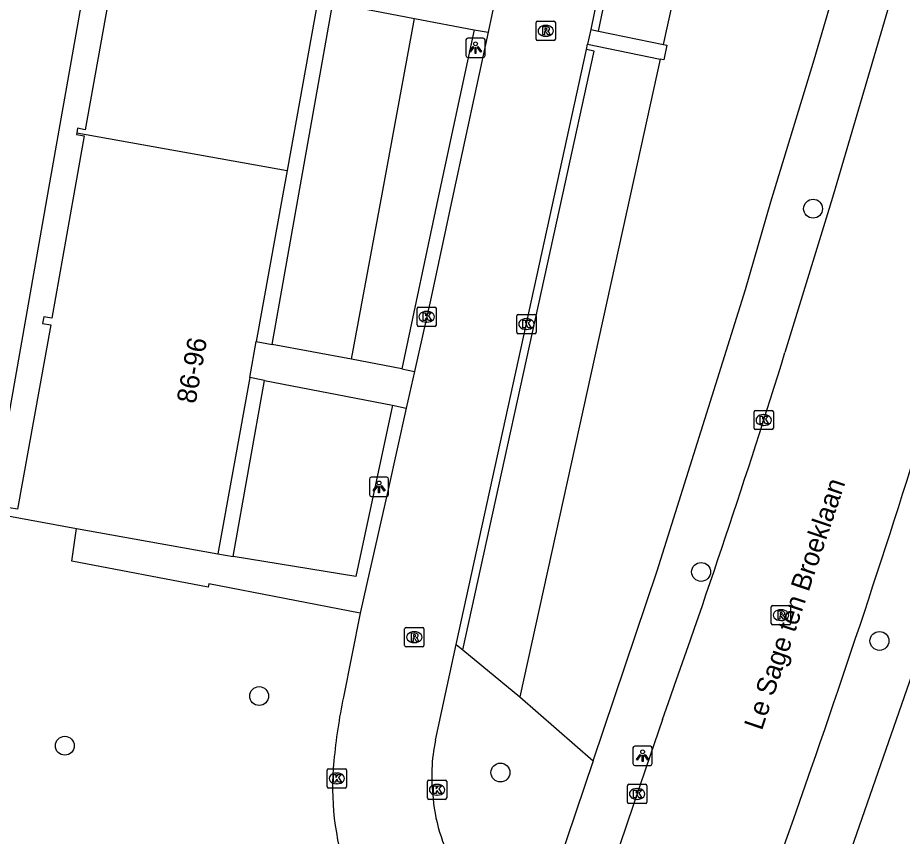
# Model space of a CAD drawing. Extents: x 161402 to 161933, y 381650 to 382313.
# Drawn here: x 161719.23 to 161765.07, y 381716.7 to 381759.14 of the extents above; entities that cross this region are included whole.
import ezdxf

# ---------------------------------------------------------------- set-up
doc = ezdxf.new("R2010")
doc.units = 0
for name, color, linetype in [('IMGEO_Boom', 7, 'Continuous'), ('IMGEO_Groenvoorziening', 7, 'Continuous'), ('IMGEO_Haag', 7, 'Continuous'), ('IMGEO_Kolk', 7, 'Continuous'), ('IMGEO_Lichtpunt', 7, 'Continuous'), ('IMGEO_Openbare_ruimte_label', 7, 'Continuous'), ('IMGEO_Pand', 7, 'Continuous'), ('IMGEO_Pand_nummerreeks', 7, 'Continuous'), ('IMGEO_Rijbaan_lokaal_open', 7, 'Continuous'), ('IMGEO_Rioolput', 7, 'Continuous'), ('IMGEO_Voetpad_halfverhard', 7, 'Continuous'), ('IMGEO_Voetpad_open', 7, 'Continuous')]:
    doc.layers.add(name, color=color, linetype=linetype)

msp = doc.modelspace()

# ---------------------------------------------------------------- linework, layer by layer
at = {"layer": 'IMGEO_Boom'}
for centre in [(161760.441, 381749.242), (161754.64, 381730.411), (161763.88, 381726.834), (161731.741, 381723.975), (161721.671, 381721.4), (161744.243, 381720.011)]:
    msp.add_circle(centre, 0.489, dxfattribs=at)
at = {"layer": 'IMGEO_Groenvoorziening'}
for points in [[(161725.367, 381800.387), (161728.333, 381792.761), (161720.782, 381750), (161715.379, 381719.409), (161702.956, 381716.799)], [(161752.695, 381757.755), (161756.802, 381776.413)], [(161736.533, 381741.432), (161738.116, 381750), (161739.797, 381759.102)], [(161752.527, 381756.994), (161750.987, 381750), (161745.247, 381723.935)], [(161742.303, 381726.365), (161745.247, 381723.935)], [(161745.247, 381723.935), (161749.043, 381720.61)]]:
    msp.add_lwpolyline(points, dxfattribs=at)
at = {"layer": 'IMGEO_Haag'}
for points in [[(161749.327, 381758.447), (161752.919, 381775.683)], [(161742.303, 381726.365), (161747.467, 381749.915), (161749.101, 381757.409), (161748.698, 381757.489)], [(161741.956, 381726.652), (161742.303, 381726.365)]]:
    msp.add_lwpolyline(points, dxfattribs=at)
at = {"layer": 'IMGEO_Kolk'}
for p, q in [((161739.921, 381743.212), (161739.921, 381744.064)), ((161739.996, 381744.138), (161740.848, 381744.138)), ((161740.409, 381743.918), (161740.434, 381743.918)), ((161740.922, 381744.064), (161740.922, 381743.212)), ((161740.432, 381743.358), (161740.407, 381743.358)), ((161745.09, 381742.836), (161745.09, 381743.688)), ((161745.165, 381743.762), (161746.017, 381743.762)), ((161745.578, 381743.542), (161745.603, 381743.542)), ((161746.091, 381743.688), (161746.091, 381742.836)), ((161740.848, 381743.138), (161739.996, 381743.138)), ((161745.601, 381742.982), (161745.576, 381742.982)), ((161746.017, 381742.762), (161745.165, 381742.762)), ((161757.46, 381738.786), (161758.312, 381738.786)), ((161757.385, 381737.86), (161757.385, 381738.712)), ((161757.873, 381738.566), (161757.898, 381738.566)), ((161758.386, 381738.712), (161758.386, 381737.86)), ((161757.896, 381738.006), (161757.871, 381738.006)), ((161758.312, 381737.786), (161757.46, 381737.786)), ((161735.266, 381719.28), (161735.266, 381720.132)), ((161735.341, 381720.206), (161736.193, 381720.206)), ((161735.754, 381719.986), (161735.779, 381719.986)), ((161736.267, 381720.132), (161736.267, 381719.28)), ((161740.461, 381718.693), (161740.461, 381719.545)), ((161740.536, 381719.619), (161741.388, 381719.619)), ((161741.462, 381719.545), (161741.462, 381718.693)), ((161736.193, 381719.206), (161735.341, 381719.206)), ((161735.777, 381719.426), (161735.752, 381719.426)), ((161740.949, 381719.399), (161740.974, 381719.399)), ((161750.825, 381718.474), (161750.825, 381719.326)), ((161750.9, 381719.4), (161751.752, 381719.4)), ((161751.313, 381719.18), (161751.338, 381719.18)), ((161751.826, 381719.326), (161751.826, 381718.474)), ((161741.388, 381718.619), (161740.536, 381718.619)), ((161740.972, 381718.839), (161740.947, 381718.839)), ((161751.336, 381718.62), (161751.311, 381718.62)), ((161751.752, 381718.4), (161750.9, 381718.4))]:
    msp.add_line(p, q, dxfattribs=at)
for points in [[(161739.921, 381743.212), (161739.921, 381744.064)], [(161739.996, 381744.138), (161740.848, 381744.138)], [(161740.242, 381743.838), (161740.365, 381743.838), (161740.365, 381743.687), (161740.495, 381743.838), (161740.659, 381743.838), (161740.513, 381743.687), (161740.666, 381743.438), (161740.514, 381743.438), (161740.429, 381743.602), (161740.365, 381743.535), (161740.365, 381743.438), (161740.242, 381743.438), (161740.242, 381743.838)], [(161740.922, 381744.064), (161740.922, 381743.212)], [(161745.09, 381742.836), (161745.09, 381743.688)], [(161745.165, 381743.762), (161746.017, 381743.762)], [(161745.411, 381743.462), (161745.534, 381743.462), (161745.534, 381743.311), (161745.664, 381743.462), (161745.828, 381743.462), (161745.682, 381743.311), (161745.835, 381743.062), (161745.683, 381743.062), (161745.598, 381743.226), (161745.534, 381743.159), (161745.534, 381743.062), (161745.411, 381743.062), (161745.411, 381743.462)], [(161746.091, 381743.688), (161746.091, 381742.836)], [(161740.848, 381743.138), (161739.996, 381743.138)], [(161746.017, 381742.762), (161745.165, 381742.762)], [(161757.46, 381738.786), (161758.312, 381738.786)], [(161757.385, 381737.86), (161757.385, 381738.712)], [(161757.706, 381738.486), (161757.829, 381738.486), (161757.829, 381738.335), (161757.959, 381738.486), (161758.123, 381738.486), (161757.977, 381738.335), (161758.13, 381738.086), (161757.978, 381738.086), (161757.893, 381738.25), (161757.829, 381738.183), (161757.829, 381738.086), (161757.706, 381738.086), (161757.706, 381738.486)], [(161758.386, 381738.712), (161758.386, 381737.86)], [(161758.312, 381737.786), (161757.46, 381737.786)], [(161735.266, 381719.28), (161735.266, 381720.132)], [(161735.341, 381720.206), (161736.193, 381720.206)], [(161736.267, 381720.132), (161736.267, 381719.28)], [(161735.587, 381719.906), (161735.71, 381719.906), (161735.71, 381719.755), (161735.84, 381719.906), (161736.004, 381719.906), (161735.858, 381719.755), (161736.011, 381719.506), (161735.859, 381719.506), (161735.774, 381719.67), (161735.71, 381719.603), (161735.71, 381719.506), (161735.587, 381719.506), (161735.587, 381719.906)], [(161740.461, 381718.693), (161740.461, 381719.545)], [(161740.536, 381719.619), (161741.388, 381719.619)], [(161741.462, 381719.545), (161741.462, 381718.693)], [(161736.193, 381719.206), (161735.341, 381719.206)], [(161740.782, 381719.319), (161740.905, 381719.319), (161740.905, 381719.168), (161741.035, 381719.319), (161741.199, 381719.319), (161741.053, 381719.168), (161741.206, 381718.919), (161741.054, 381718.919), (161740.969, 381719.083), (161740.905, 381719.016), (161740.905, 381718.919), (161740.782, 381718.919), (161740.782, 381719.319)], [(161750.825, 381718.474), (161750.825, 381719.326)], [(161750.9, 381719.4), (161751.752, 381719.4)], [(161751.146, 381719.1), (161751.269, 381719.1), (161751.269, 381718.949), (161751.399, 381719.1), (161751.563, 381719.1), (161751.417, 381718.949), (161751.57, 381718.7), (161751.418, 381718.7), (161751.333, 381718.864), (161751.269, 381718.797), (161751.269, 381718.7), (161751.146, 381718.7), (161751.146, 381719.1)], [(161751.826, 381719.326), (161751.826, 381718.474)], [(161741.388, 381718.619), (161740.536, 381718.619)], [(161751.752, 381718.4), (161750.9, 381718.4)]]:
    msp.add_lwpolyline(points, dxfattribs=at)
for centre, start, end in [((161739.998, 381744.062), 91.552, 178.448), ((161739.998, 381744.062), 91.552, 178.448), ((161740.846, 381744.062), 1.552, 88.448), ((161740.846, 381744.062), 1.552, 88.448), ((161745.167, 381743.686), 91.552, 178.448), ((161745.167, 381743.686), 91.552, 178.448), ((161746.015, 381743.686), 1.552, 88.448), ((161746.015, 381743.686), 1.552, 88.448), ((161739.998, 381743.214), 181.552, 268.448), ((161739.998, 381743.214), 181.552, 268.448), ((161740.846, 381743.214), 271.552, 358.448), ((161740.846, 381743.214), 271.552, 358.448), ((161745.167, 381742.838), 181.552, 268.448), ((161745.167, 381742.838), 181.552, 268.448), ((161746.015, 381742.838), 271.552, 358.448), ((161746.015, 381742.838), 271.552, 358.448), ((161757.462, 381738.71), 91.552, 178.448), ((161757.462, 381738.71), 91.552, 178.448), ((161758.31, 381738.71), 1.552, 88.448), ((161758.31, 381738.71), 1.552, 88.448), ((161757.462, 381737.862), 181.552, 268.448), ((161757.462, 381737.862), 181.552, 268.448), ((161758.31, 381737.862), 271.552, 358.448), ((161758.31, 381737.862), 271.552, 358.448), ((161735.343, 381720.13), 91.552, 178.448), ((161735.343, 381720.13), 91.552, 178.448), ((161736.191, 381720.13), 1.552, 88.448), ((161736.191, 381720.13), 1.552, 88.448), ((161740.538, 381719.543), 91.552, 178.448), ((161740.538, 381719.543), 91.552, 178.448), ((161741.386, 381719.543), 1.552, 88.448), ((161741.386, 381719.543), 1.552, 88.448), ((161735.343, 381719.282), 181.552, 268.448), ((161735.343, 381719.282), 181.552, 268.448), ((161736.191, 381719.282), 271.552, 358.448), ((161736.191, 381719.282), 271.552, 358.448), ((161750.902, 381719.324), 91.552, 178.448), ((161750.902, 381719.324), 91.552, 178.448), ((161751.75, 381719.324), 1.552, 88.448), ((161751.75, 381719.324), 1.552, 88.448), ((161740.538, 381718.695), 181.552, 268.448), ((161740.538, 381718.695), 181.552, 268.448), ((161741.386, 381718.695), 271.552, 358.448), ((161741.386, 381718.695), 271.552, 358.448), ((161750.902, 381718.476), 181.552, 268.448), ((161750.902, 381718.476), 181.552, 268.448), ((161751.75, 381718.476), 271.552, 358.448), ((161751.75, 381718.476), 271.552, 358.448)]:
    msp.add_arc(centre, 0.0765, start, end, dxfattribs=at)
for centre, major_axis, ratio, start_param, end_param in [((161740.408, 381743.638), (-0.387, 0.002), 0.722429, 4.712389, 7.853982), ((161740.433, 381743.638), (-0.39, 0.002), 0.717154, 1.570796, 4.712389), ((161745.577, 381743.262), (-0.387, 0.002), 0.722429, 4.712389, 7.853982), ((161745.602, 381743.262), (-0.39, 0.002), 0.717154, 1.570796, 4.712389), ((161757.872, 381738.286), (-0.387, 0.002), 0.722429, 4.712389, 7.853982), ((161757.897, 381738.286), (-0.39, 0.002), 0.717154, 1.570796, 4.712389), ((161735.753, 381719.706), (-0.387, 0.002), 0.722429, 4.712389, 7.853982), ((161735.778, 381719.706), (-0.39, 0.002), 0.717154, 1.570796, 4.712389), ((161740.948, 381719.119), (-0.387, 0.002), 0.722429, 4.712389, 7.853982), ((161740.973, 381719.119), (-0.39, 0.002), 0.717154, 1.570796, 4.712389), ((161751.312, 381718.9), (-0.387, 0.002), 0.722429, 4.712389, 7.853982), ((161751.337, 381718.9), (-0.39, 0.002), 0.717154, 1.570796, 4.712389)]:
    msp.add_ellipse(centre, major_axis=major_axis, ratio=ratio, start_param=start_param, end_param=end_param, dxfattribs=at)
at = {"layer": 'IMGEO_Lichtpunt'}
for p, q in [((161743.356, 381758.082), (161742.548, 381758.082)), ((161743.356, 381758.082), (161742.548, 381758.082)), ((161742.454, 381757.987), (161742.454, 381757.18)), ((161742.454, 381757.987), (161742.454, 381757.18)), ((161743.45, 381757.18), (161743.45, 381757.987)), ((161743.45, 381757.18), (161743.45, 381757.987)), ((161742.548, 381757.086), (161743.356, 381757.086)), ((161742.548, 381757.086), (161743.356, 381757.086)), ((161737.455, 381735.223), (161737.455, 381734.416)), ((161737.455, 381735.223), (161737.455, 381734.416)), ((161738.357, 381735.318), (161737.549, 381735.318)), ((161738.357, 381735.318), (161737.549, 381735.318)), ((161738.451, 381734.416), (161738.451, 381735.223)), ((161738.451, 381734.416), (161738.451, 381735.223)), ((161737.549, 381734.322), (161738.357, 381734.322)), ((161737.549, 381734.322), (161738.357, 381734.322)), ((161752.012, 381721.379), (161751.204, 381721.379)), ((161752.012, 381721.379), (161751.204, 381721.379)), ((161751.11, 381721.284), (161751.11, 381720.477)), ((161751.11, 381721.284), (161751.11, 381720.477)), ((161752.106, 381720.477), (161752.106, 381721.284)), ((161752.106, 381720.477), (161752.106, 381721.284)), ((161751.204, 381720.383), (161752.012, 381720.383)), ((161751.204, 381720.383), (161752.012, 381720.383))]:
    msp.add_line(p, q, dxfattribs=at)
for points in [[(161742.828, 381757.651), (161742.867, 381757.623), (161742.679, 381757.361), (161742.641, 381757.388), (161742.828, 381757.651)], [(161742.93, 381757.603), (161742.977, 381757.603), (161742.977, 381757.281), (161742.93, 381757.281), (161742.93, 381757.603)], [(161743.04, 381757.623), (161743.078, 381757.65), (161743.265, 381757.388), (161743.226, 381757.36), (161743.04, 381757.623)], [(161737.829, 381734.887), (161737.868, 381734.859), (161737.68, 381734.597), (161737.642, 381734.624), (161737.829, 381734.887)], [(161737.931, 381734.839), (161737.978, 381734.839), (161737.978, 381734.517), (161737.931, 381734.517), (161737.931, 381734.839)], [(161738.041, 381734.859), (161738.079, 381734.886), (161738.266, 381734.624), (161738.227, 381734.596), (161738.041, 381734.859)], [(161751.484, 381720.948), (161751.523, 381720.92), (161751.335, 381720.658), (161751.297, 381720.685), (161751.484, 381720.948)], [(161751.586, 381720.9), (161751.633, 381720.9), (161751.633, 381720.578), (161751.586, 381720.578), (161751.586, 381720.9)], [(161751.696, 381720.92), (161751.734, 381720.947), (161751.921, 381720.685), (161751.882, 381720.657), (161751.696, 381720.92)]]:
    msp.add_lwpolyline(points, dxfattribs=at)
for centre in [(161742.953, 381757.785), (161737.954, 381735.021), (161751.609, 381721.082)]:
    msp.add_circle(centre, 0.0994, dxfattribs=at)
for centre, start, end in [((161742.548, 381757.987), 90, 180), ((161742.548, 381757.987), 90, 180), ((161743.356, 381757.987), 0, 90), ((161743.356, 381757.987), 0, 90), ((161742.548, 381757.18), 180, 270), ((161742.548, 381757.18), 180, 270), ((161743.356, 381757.18), 270, 0), ((161743.356, 381757.18), 270, 360), ((161737.549, 381735.223), 90, 180), ((161737.549, 381735.223), 90, 180), ((161738.357, 381735.223), 0, 90), ((161738.357, 381735.223), 0, 90), ((161737.549, 381734.416), 180, 270), ((161737.549, 381734.416), 180, 270), ((161738.357, 381734.416), 270, 0), ((161738.357, 381734.416), 270, 360), ((161751.204, 381721.284), 90, 180), ((161751.204, 381721.284), 90, 180), ((161752.012, 381721.284), 0, 90), ((161752.012, 381721.284), 0, 90), ((161751.204, 381720.477), 180, 270), ((161751.204, 381720.477), 180, 270), ((161752.012, 381720.477), 270, 0), ((161752.012, 381720.477), 270, 360)]:
    msp.add_arc(centre, 0.0946, start, end, dxfattribs=at)
at = {"layer": 'IMGEO_Pand'}
for points in [[(161725.892, 381773.039), (161725.859, 381772.854), (161726.26, 381772.781), (161724.523, 381763.142), (161724.114, 381763.215), (161724.064, 381762.939), (161724.443, 381762.871), (161722.724, 381753.337), (161722.338, 381753.407), (161722.297, 381753.177)], [(161734.783, 381760.053), (161733.19, 381751.213)], [(161722.297, 381753.177), (161722.28, 381753.082), (161722.68, 381753.011), (161722.143, 381750), (161720.996, 381743.567), (161720.586, 381743.641), (161720.524, 381743.295), (161720.94, 381743.22), (161719.217, 381733.661), (161718.794, 381733.737), (161718.717, 381733.311), (161722.279, 381732.669)], [(161722.297, 381753.177), (161733.19, 381751.213)], [(161733.19, 381751.213), (161732.971, 381750), (161731.594, 381742.363)], [(161731.255, 381740.488), (161731.594, 381742.363)], [(161731.255, 381740.488), (161729.607, 381731.348)], [(161722.279, 381732.669), (161729.607, 381731.348)]]:
    msp.add_lwpolyline(points, dxfattribs=at)
at = {"layer": 'IMGEO_Rijbaan_lokaal_open'}
for points in [[(161754.814, 381786.734), (161752.712, 381777.049), (161748.925, 381758.53)], [(161770.158, 381780.913), (161765.505, 381763.644), (161761.5, 381750), (161761.259, 381749.201), (161758.985, 381741.778)], [(161743.993, 381760.2), (161743.602, 381758.386)], [(161748.925, 381758.53), (161748.758, 381757.763)], [(161743.602, 381758.386), (161741.798, 381750), (161740.649, 381744.661), (161739.789, 381740.808)], [(161748.698, 381757.489), (161748.758, 381757.763)], [(161741.956, 381726.652), (161747.061, 381750), (161748.698, 381757.489)], [(161739.789, 381740.808), (161739.363, 381738.9)], [(161739.363, 381738.9), (161738.423, 381734.691), (161737.326, 381729.802), (161736.974, 381728.265)], [(161736.974, 381728.265), (161736.105, 381723.922)], [(161740.88, 381721.689), (161741.956, 381726.652)], [(161752.637, 381722.762), (161751.781, 381720.237), (161748.444, 381710.397)], [(161750.867, 381693.658), (161751.631, 381695.709), (161754.863, 381704.566), (161757.922, 381713.379), (161759.437, 381717.619), (161760.349, 381720.224)]]:
    msp.add_lwpolyline(points, dxfattribs=at)
for centre, radius, start, end in [((161312.649, 381880.208), 467.31, 340.31066, 342.76883), ((161210.71, 381911.237), 581.883, 340.83641, 343.084251), ((161766.318, 381717.777), 30.832, 168.5045, 174.7269), ((161749.719, 381719.81), 9.037, 167.9975, 187.3155), ((161749.342, 381719.214), 13.796, 174.1902, 198.9774), ((161749.343, 381719.411), 8.62, 185.002, 211.8498)]:
    msp.add_arc(centre, radius, start, end, dxfattribs=at)
at = {"layer": 'IMGEO_Rioolput'}
for p, q in [((161746.165, 381758.963), (161747.017, 381758.963)), ((161746.09, 381758.037), (161746.09, 381758.889)), ((161746.578, 381758.743), (161746.603, 381758.743)), ((161747.091, 381758.889), (161747.091, 381758.037)), ((161746.601, 381758.183), (161746.576, 381758.183)), ((161747.017, 381757.963), (161746.165, 381757.963)), ((161758.278, 381727.745), (161758.278, 381728.597)), ((161758.353, 381728.671), (161759.205, 381728.671)), ((161758.766, 381728.451), (161758.791, 381728.451)), ((161759.279, 381728.597), (161759.279, 381727.745)), ((161758.789, 381727.891), (161758.764, 381727.891)), ((161739.281, 381726.601), (161739.281, 381727.453)), ((161739.356, 381727.527), (161740.208, 381727.527)), ((161740.282, 381727.453), (161740.282, 381726.601)), ((161759.205, 381727.671), (161758.353, 381727.671)), ((161739.769, 381727.307), (161739.794, 381727.307)), ((161740.208, 381726.527), (161739.356, 381726.527)), ((161739.792, 381726.747), (161739.767, 381726.747))]:
    msp.add_line(p, q, dxfattribs=at)
for points in [[(161746.165, 381758.963), (161747.017, 381758.963)], [(161746.09, 381758.037), (161746.09, 381758.889)], [(161746.679, 381758.661), (161746.427, 381758.663), (161746.427, 381758.263)], [(161746.605, 381758.582), (161746.551, 381758.582), (161746.551, 381758.501)], [(161746.551, 381758.501), (161746.603, 381758.501)], [(161747.091, 381758.889), (161747.091, 381758.037)], [(161746.427, 381758.263), (161746.551, 381758.263), (161746.551, 381758.425), (161746.562, 381758.425)], [(161746.609, 381758.396), (161746.68, 381758.263), (161746.82, 381758.263), (161746.755, 381758.389)], [(161747.017, 381757.963), (161746.165, 381757.963)], [(161758.278, 381727.745), (161758.278, 381728.597)], [(161758.353, 381728.671), (161759.205, 381728.671)], [(161758.867, 381728.369), (161758.615, 381728.371), (161758.615, 381727.971)], [(161758.793, 381728.29), (161758.739, 381728.29), (161758.739, 381728.209)], [(161759.279, 381728.597), (161759.279, 381727.745)], [(161758.615, 381727.971), (161758.739, 381727.971), (161758.739, 381728.133), (161758.75, 381728.133)], [(161758.739, 381728.209), (161758.791, 381728.209)], [(161758.797, 381728.104), (161758.868, 381727.971), (161759.008, 381727.971), (161758.943, 381728.097)], [(161739.281, 381726.601), (161739.281, 381727.453)], [(161739.356, 381727.527), (161740.208, 381727.527)], [(161740.282, 381727.453), (161740.282, 381726.601)], [(161759.205, 381727.671), (161758.353, 381727.671)], [(161739.87, 381727.225), (161739.618, 381727.227), (161739.618, 381726.827)], [(161739.618, 381726.827), (161739.742, 381726.827), (161739.742, 381726.989), (161739.753, 381726.989)], [(161739.796, 381727.146), (161739.742, 381727.146), (161739.742, 381727.065)], [(161739.742, 381727.065), (161739.794, 381727.065)], [(161739.8, 381726.96), (161739.871, 381726.827), (161740.011, 381726.827), (161739.946, 381726.953)], [(161740.208, 381726.527), (161739.356, 381726.527)]]:
    msp.add_lwpolyline(points, dxfattribs=at)
for centre, radius, start, end in [((161746.167, 381758.887), 0.0765, 91.552, 178.448), ((161746.167, 381758.887), 0.0765, 91.552, 178.448), ((161747.015, 381758.887), 0.0765, 1.552, 88.448), ((161747.015, 381758.887), 0.0765, 1.552, 88.448), ((161746.587, 381758.69), 0.19, 274.7715, 282.9687), ((161746.611, 381758.486), 0.0964, 77.0061, 93.1865), ((161746.625, 381758.543), 0.0378, 276.6634, 79.6772), ((161746.678, 381758.551), 0.109, 350.3612, 89.416), ((161746.676, 381758.551), 0.112, 277.5842, 350.9817), ((161746.167, 381758.039), 0.0765, 181.552, 268.448), ((161746.167, 381758.039), 0.0765, 181.552, 268.448), ((161746.561, 381758.372), 0.0533, 26.0293, 88.6989), ((161746.66, 381758.336), 0.108, 29.5134, 73.7905), ((161747.015, 381758.039), 0.0765, 271.552, 358.448), ((161747.015, 381758.039), 0.0765, 271.552, 358.448), ((161758.355, 381728.595), 0.0765, 91.552, 178.448), ((161758.355, 381728.595), 0.0765, 91.552, 178.448), ((161758.799, 381728.194), 0.0964, 77.0061, 93.1865), ((161758.813, 381728.251), 0.0378, 276.6634, 79.6772), ((161758.866, 381728.259), 0.109, 350.3612, 89.416), ((161758.864, 381728.259), 0.112, 277.5842, 350.9817), ((161759.203, 381728.595), 0.0765, 1.552, 88.448), ((161759.203, 381728.595), 0.0765, 1.552, 88.448), ((161758.749, 381728.08), 0.0533, 26.0293, 88.6989), ((161758.775, 381728.398), 0.19, 274.7715, 282.9687), ((161758.848, 381728.044), 0.108, 29.5134, 73.7905), ((161739.358, 381727.451), 0.0765, 91.552, 178.448), ((161739.358, 381727.451), 0.0765, 91.552, 178.448), ((161740.206, 381727.451), 0.0765, 1.552, 88.448), ((161740.206, 381727.451), 0.0765, 1.552, 88.448), ((161758.355, 381727.747), 0.0765, 181.552, 268.448), ((161758.355, 381727.747), 0.0765, 181.552, 268.448), ((161759.203, 381727.747), 0.0765, 271.552, 358.448), ((161759.203, 381727.747), 0.0765, 271.552, 358.448), ((161739.752, 381726.936), 0.0533, 26.0293, 88.6989), ((161739.778, 381727.254), 0.19, 274.7715, 282.9687), ((161739.802, 381727.05), 0.0964, 77.0061, 93.1865), ((161739.816, 381727.107), 0.0378, 276.6634, 79.6772), ((161739.869, 381727.115), 0.109, 350.3612, 89.416), ((161739.867, 381727.115), 0.112, 277.5842, 350.9817), ((161739.851, 381726.9), 0.108, 29.5134, 73.7905), ((161739.358, 381726.603), 0.0765, 181.552, 268.448), ((161739.358, 381726.603), 0.0765, 181.552, 268.448), ((161740.206, 381726.603), 0.0765, 271.552, 358.448), ((161740.206, 381726.603), 0.0765, 271.552, 358.448)]:
    msp.add_arc(centre, radius, start, end, dxfattribs=at)
for centre, major_axis, ratio, start_param, end_param in [((161746.577, 381758.463), (-0.387, 0.002), 0.722429, 4.712389, 7.853982), ((161746.602, 381758.463), (-0.39, 0.002), 0.717154, 1.570796, 4.712389), ((161758.765, 381728.171), (-0.387, 0.002), 0.722429, 4.712389, 7.853982), ((161758.79, 381728.171), (-0.39, 0.002), 0.717154, 1.570796, 4.712389), ((161739.768, 381727.027), (-0.387, 0.002), 0.722429, 4.712389, 7.853982), ((161739.793, 381727.027), (-0.39, 0.002), 0.717154, 1.570796, 4.712389)]:
    msp.add_ellipse(centre, major_axis=major_axis, ratio=ratio, start_param=start_param, end_param=end_param, dxfattribs=at)
at = {"layer": 'IMGEO_Voetpad_halfverhard'}
for points in [[(161732.415, 381742.208), (161733.8, 381750), (161735.559, 381759.906)], [(161730.391, 381731.218), (161732.017, 381740.34)]]:
    msp.add_lwpolyline(points, dxfattribs=at)
at = {"layer": 'IMGEO_Voetpad_open'}
for points in [[(161749.043, 381720.61), (161752.356, 381730.461), (161755.4, 381740.142), (161756.942, 381745.046), (161758.254, 381749.595), (161760.494, 381756.959), (161763.257, 381766.412), (161766.489, 381778.241)], [(161774.933, 381686.404), (161758.095, 381688.61), (161755.465, 381688.954), (161753.951, 381692.163), (161755.462, 381695.988), (161767.515, 381730.653), (161773.48, 381750), (161778.317, 381767.408)], [(161735.559, 381759.906), (161739.797, 381759.102)], [(161739.797, 381759.102), (161742.874, 381758.518)], [(161742.874, 381758.518), (161741.06, 381750), (161739.131, 381740.943)], [(161742.874, 381758.518), (161743.602, 381758.386)], [(161748.925, 381758.53), (161749.327, 381758.447)], [(161749.327, 381758.447), (161752.695, 381757.755)], [(161748.758, 381757.763), (161752.527, 381756.994)], [(161752.695, 381757.755), (161752.861, 381757.721), (161752.71, 381756.957), (161752.527, 381756.994)], [(161731.594, 381742.363), (161732.415, 381742.208)], [(161736.533, 381741.432), (161732.415, 381742.208)], [(161739.131, 381740.943), (161736.533, 381741.432)], [(161739.131, 381740.943), (161739.789, 381740.808)], [(161732.017, 381740.34), (161731.255, 381740.488)], [(161732.017, 381740.34), (161738.646, 381739.048)], [(161738.646, 381739.048), (161736.749, 381730.166), (161730.391, 381731.218)], [(161738.646, 381739.048), (161739.363, 381738.9)], [(161736.974, 381728.265), (161729.137, 381729.786), (161729.096, 381729.626), (161722.028, 381730.97), (161722.279, 381732.669)], [(161729.607, 381731.348), (161730.391, 381731.218)], [(161749.043, 381720.61), (161745.877, 381711.196)]]:
    msp.add_lwpolyline(points, dxfattribs=at)

# ---------------------------------------------------------------- texts
at = {"layer": 'IMGEO_Openbare_ruimte_label'}
msp.add_text('Le Sage ten Broeklaan', height=1, rotation=71.402, dxfattribs=at).set_placement((161757.787, 381722.153))
at = {"layer": 'IMGEO_Pand_nummerreeks'}
msp.add_text('86-96', height=1, rotation=79.7786, dxfattribs=at).set_placement((161728.443, 381739.094))

doc.saveas('drawing.dxf')
